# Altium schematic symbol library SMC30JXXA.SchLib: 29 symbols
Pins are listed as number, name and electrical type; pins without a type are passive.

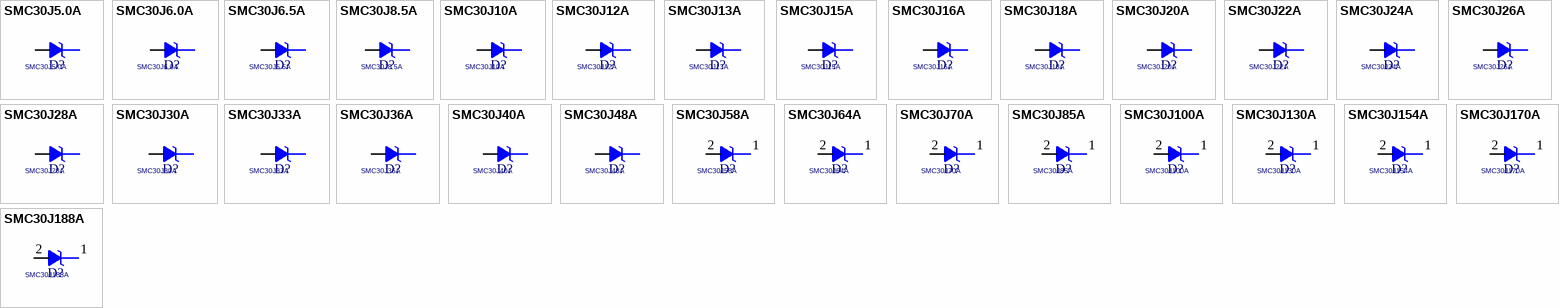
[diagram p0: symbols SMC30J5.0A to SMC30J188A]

## SMC30J5.0A
designator D?
footprint ST_SMC
pins: 1 K, 2 A

## SMC30J6.0A
designator D?
footprint ST_SMC
pins: 1 K, 2 A

## SMC30J6.5A
designator D?
footprint ST_SMC
pins: 1 K, 2 A

## SMC30J8.5A
designator D?
footprint ST_SMC
pins: 1 K, 2 A

## SMC30J10A
designator D?
footprint ST_SMC
pins: 1 K, 2 A

## SMC30J12A
designator D?
footprint ST_SMC
pins: 1 K, 2 A

## SMC30J13A
designator D?
footprint ST_SMC
pins: 1 K, 2 A

## SMC30J15A
designator D?
footprint ST_SMC
pins: 1 K, 2 A

## SMC30J16A
designator D?
footprint ST_SMC
pins: 1 K, 2 A

## SMC30J18A
designator D?
footprint ST_SMC
pins: 1 K, 2 A

## SMC30J20A
designator D?
footprint ST_SMC
pins: 1 K, 2 A

## SMC30J22A
designator D?
footprint ST_SMC
pins: 1 K, 2 A

## SMC30J24A
designator D?
footprint ST_SMC
pins: 1 K, 2 A

## SMC30J26A
designator D?
footprint ST_SMC
pins: 1 K, 2 A

## SMC30J28A
designator D?
footprint ST_SMC
pins: 1 K, 2 A

## SMC30J30A
designator D?
footprint ST_SMC
pins: 1 K, 2 A

## SMC30J33A
designator D?
footprint ST_SMC
pins: 1 K, 2 A

## SMC30J36A
designator D?
footprint ST_SMC
pins: 1 K, 2 A

## SMC30J40A
designator D?
footprint ST_SMC
pins: 1 K, 2 A

## SMC30J48A
designator D?
footprint ST_SMC
pins: 1 K, 2 A

## SMC30J58A
designator D?
footprint ST_SMC
pins: 1 K, 2 A

## SMC30J64A
designator D?
footprint ST_SMC
pins: 1 K, 2 A

## SMC30J70A
designator D?
footprint ST_SMC
pins: 1 K, 2 A

## SMC30J85A
designator D?
footprint ST_SMC
pins: 1 K, 2 A

## SMC30J100A
designator D?
footprint ST_SMC
pins: 1 K, 2 A

## SMC30J130A
designator D?
footprint ST_SMC
pins: 1 K, 2 A

## SMC30J154A
designator D?
footprint ST_SMC
pins: 1 K, 2 A

## SMC30J170A
designator D?
footprint ST_SMC
pins: 1 K, 2 A

## SMC30J188A
designator D?
footprint ST_SMC
pins: 1 K, 2 A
